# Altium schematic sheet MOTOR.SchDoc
size 558 x 431 mm; Engineer: Nicholas Oborny; Revision: A.1; Name: Nicholas Oborny; Start Date: 7/23/2012
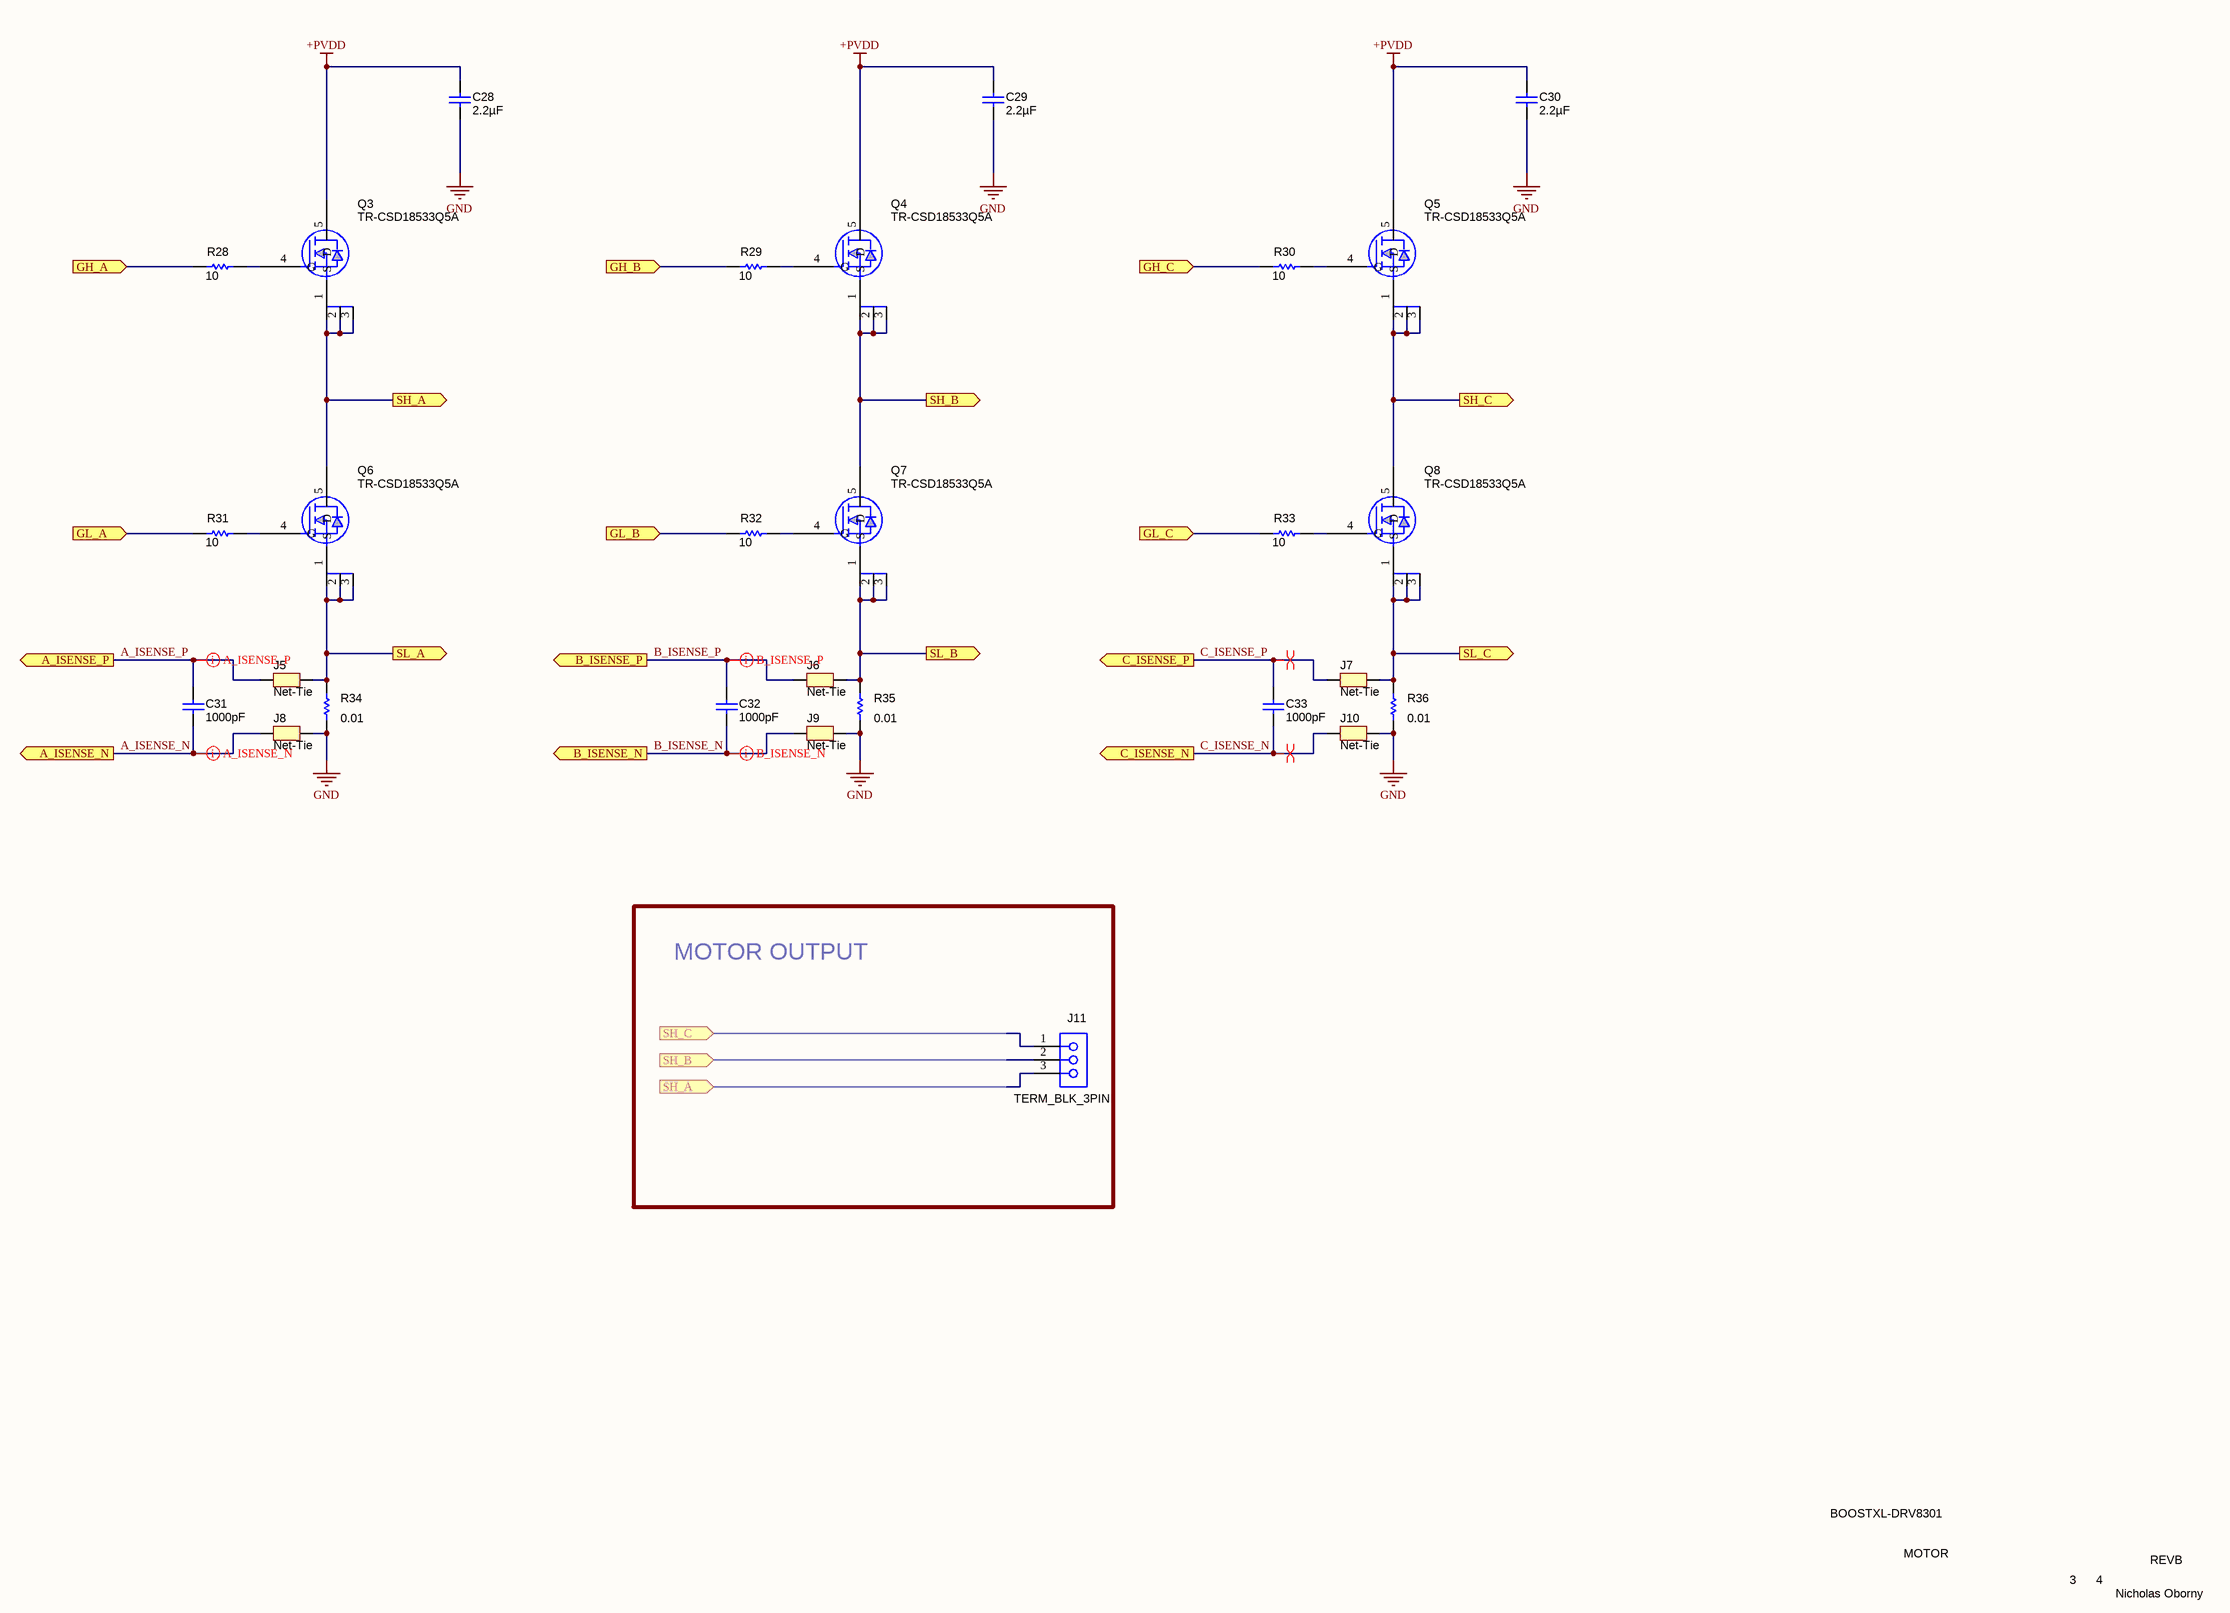
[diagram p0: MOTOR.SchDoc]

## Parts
C28  ValueDisplayed: 2.2µF  [1210L]  (hidden comment: GRM32ER72A225KA35L)
C29  ValueDisplayed: 2.2µF  [1210L]  (hidden comment: GRM32ER72A225KA35L)
C30  ValueDisplayed: 2.2µF  [1210L]  (hidden comment: GRM32ER72A225KA35L)
C31  ValueDisplayed: 1000pF  [0603]  (hidden comment: C0603C102J5GAC)
C32  ValueDisplayed: 1000pF  [0603]  (hidden comment: C0603C102J5GAC)
C33  ValueDisplayed: 1000pF  [0603]  (hidden comment: C0603C102J5GAC)
J5  Net-Tie  [Net-Tie_10mil]  (net tie, no BOM)
J6  Net-Tie  [Net-Tie_10mil]  (net tie, no BOM)
J7  Net-Tie  [Net-Tie_10mil]  (net tie, no BOM)
J8  Net-Tie  [Net-Tie_10mil]  (net tie, no BOM)
J9  Net-Tie  [Net-Tie_10mil]  (net tie, no BOM)
J10  Net-Tie  [Net-Tie_10mil]  (net tie, no BOM)
J11  TERM_BLK_3PIN  [CONN_ED120_3DS]
Q3  TR-CSD18533Q5A  [QFN5X6MM]
Q4  TR-CSD18533Q5A  [QFN5X6MM]
Q5  TR-CSD18533Q5A  [QFN5X6MM]
Q6  TR-CSD18533Q5A  [QFN5X6MM]
Q7  TR-CSD18533Q5A  [QFN5X6MM]
Q8  TR-CSD18533Q5A  [QFN5X6MM]
R28  value 10  [0603L]  (hidden comment: CRCW060310R0JNEA)
R29  value 10  [0603L]  (hidden comment: CRCW060310R0JNEA)
R30  value 10  [0603L]  (hidden comment: CRCW060310R0JNEA)
R31  value 10  [0603L]  (hidden comment: CRCW060310R0JNEA)
R32  value 10  [0603L]  (hidden comment: CRCW060310R0JNEA)
R33  value 10  [0603L]  (hidden comment: CRCW060310R0JNEA)
R34  value 0.01  [2512M]  (hidden comment: CRA2512-FZ-R010ELF)
R35  value 0.01  [2512M]  (hidden comment: CRA2512-FZ-R010ELF)
R36  value 0.01  [2512M]  (hidden comment: CRA2512-FZ-R010ELF)

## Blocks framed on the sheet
MOTOR OUTPUT: J11

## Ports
A_ISENSE_N, A_ISENSE_P, B_ISENSE_N, B_ISENSE_P, C_ISENSE_N, C_ISENSE_P, GH_A, GH_B, GH_C, GL_A, GL_B, GL_C, SH_A, SH_B, SH_C, SL_A, SL_B, SL_C

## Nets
+PVDD: C28.1 C29.1 C30.1 Q3.5(D) Q4.5(D) Q5.5(D)
GND: C28.2 C29.2 C30.2 J8.1 J9.1 J10.1 R34.1 R35.1 R36.1
A_ISENSE_N: C31.2 J8.2 ; port A_ISENSE_N
A_ISENSE_P: C31.1 J5.2 ; port A_ISENSE_P
B_ISENSE_N: C32.2 J9.2 ; port B_ISENSE_N
B_ISENSE_P: C32.1 J6.2 ; port B_ISENSE_P
C_ISENSE_N: C33.2 J10.2 ; port C_ISENSE_N
C_ISENSE_P: C33.1 J7.2 ; port C_ISENSE_P
GH_A: R28.1 ; port GH_A
GH_B: R29.1 ; port GH_B
GH_C: R30.1 ; port GH_C
GL_A: R31.1 ; port GL_A
GL_B: R32.1 ; port GL_B
GL_C: R33.1 ; port GL_C
SH_A: J11.3 Q3.1(S) Q3.2 Q3.3 Q6.5(D) ; port SH_A
SH_B: J11.2 Q4.1(S) Q4.2 Q4.3 Q7.5(D) ; port SH_B
SH_C: J11.1 Q5.1(S) Q5.2 Q5.3 Q8.5(D) ; port SH_C
SL_A: J5.1 Q6.1(S) Q6.2 Q6.3 R34.2 ; port SL_A
SL_B: J6.1 Q7.1(S) Q7.2 Q7.3 R35.2 ; port SL_B
SL_C: J7.1 Q8.1(S) Q8.2 Q8.3 R36.2 ; port SL_C
NetQ3_4: Q3.4(G) R28.2
NetQ4_4: Q4.4(G) R29.2
NetQ5_4: Q5.4(G) R30.2
NetQ6_4: Q6.4(G) R31.2
NetQ7_4: Q7.4(G) R32.2
NetQ8_4: Q8.4(G) R33.2

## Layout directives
differential pair: A_ISENSE_N, A_ISENSE_P, B_ISENSE_N, B_ISENSE_P, C_ISENSE_N, C_ISENSE_P

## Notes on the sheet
- BOOSTXL-DRV8301
- MOTOR
- 3
- 4
- REVB
- Nicholas Oborny

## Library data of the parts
C28-C30 = GRM32ER72A225KA35L: CAP, CERM, 2.2uF, 100V, +/-10%, X7R, 1210; Manufacturer: MuRata; Polarized: N; CompType: Capacitor; U/M: EA; Cap_F: 0.0000022; Tolerance_%: 10; ESR_Ohm: 0.007; Value1: 0.007 ohm; VDC_V: 100; IRMS_A: 4.4; TaMin_C: -55; TaMax_C: 125; Cap_Case: 1210
C31-C33 = C0603C102J5GAC: CAP, CERM, 1000pF, 50V, +/-5%, C0G/NP0, 0603; Manufacturer: Kemet; Polarized: N; CompType: Capacitor; U/M: EA; Cap_F: 0.000000001; Tolerance_%: 5; Value1: Unknown; VDC_V: 50; TaMin_C: -55; TaMax_C: 125
J5-J10 = Net-Tie: Single point connection between nets.; SymbolCreator: codlsc
J11 = ED120/3DS: TERMINAL BLOCK 5.08MM VERT 3POS; PartNumber: OSTTA034163; Manufacturer: On-Shore Technology; SymbolCreator: a0412235; U/M: EA; Value: 3 Pin Header
Q3-Q8 = TR-CSD18533Q5A: MOSFET, N-Chan, 60V, 18A, 6.1 mOhm; Manufacturer: TI; Area: 86800
R28-R33 = CRCW060310R0JNEA: RES, 10 ohm, 5%, 0.1W, 0603; Manufacturer: Vishay-Dale; CompType: Resistor; Value_Code: 10R0; Tolerance_%: 5; Power_W: 0.1; VDC_V: 75; TempCo: 200 ppm/C; EIA_Code: E24; U/M: EA
R34-R36 = CRA2512-FZ-R010ELF: RES, 0.01 ohm, 1%, 3W, 2512; Manufacturer: Bourns; CompType: Resistor; Value_Code: R010; Tolerance_%: 1; Power_W: 3; TempCo: 75 ppm/C; EIA_Code: E96; U/M: EA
